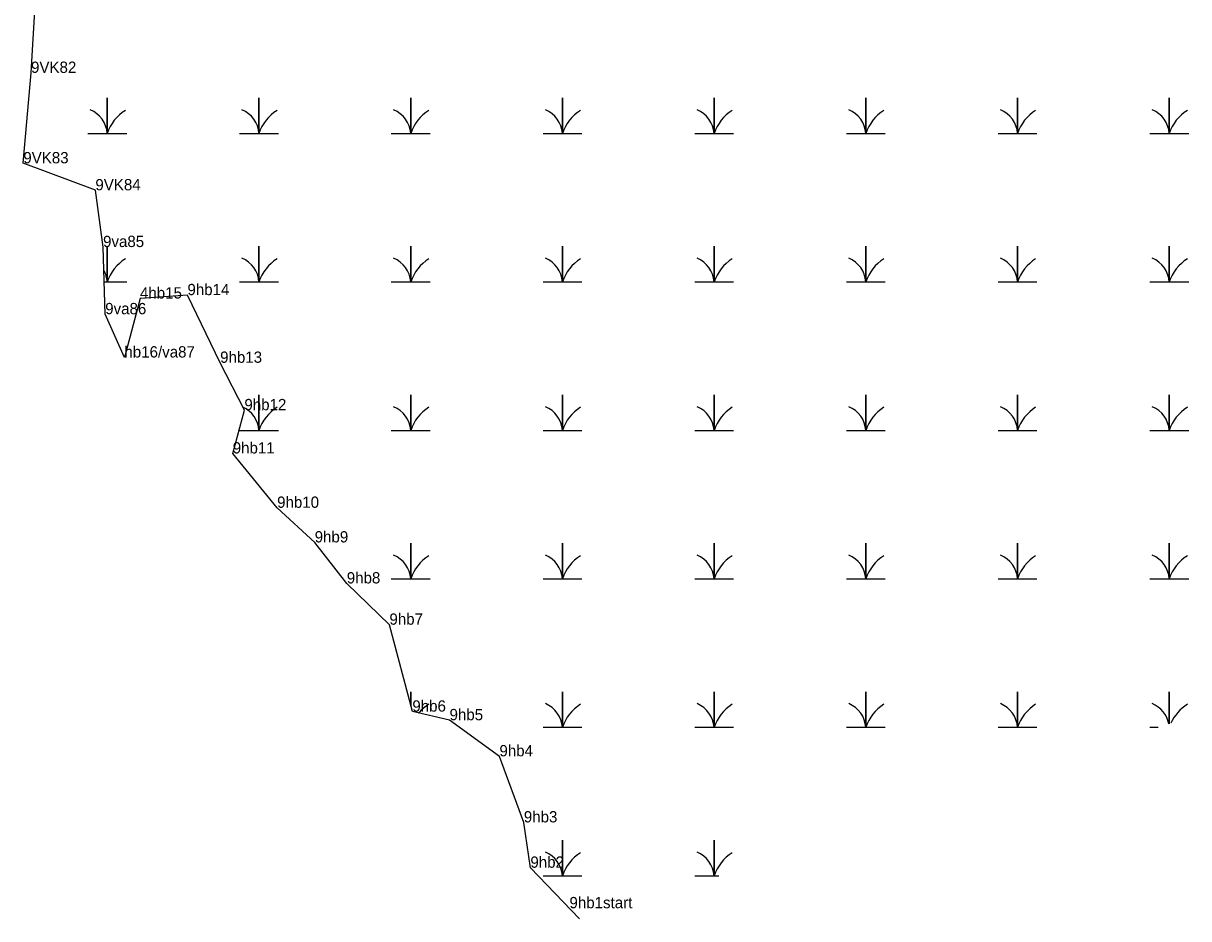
# Model space of a CAD drawing. Extents: x 2072529 to 2268796, y 436423 to 470406.
# Drawn here: x 2205507 to 2206024, y 446974 to 447371 of the extents above; entities that cross this region are included whole.
import ezdxf

# ---------------------------------------------------------------- set-up
doc = ezdxf.new("R2010")
doc.units = 0
for name, color, linetype in [('Exist Environmental Wetland Boundary Cogo Comment', 7, 'Continuous'), ('Exist Environmental Wetland Boundary Cogo Point CELL', 7, 'Continuous'), ('Old_Level_20', 7, 'Continuous')]:
    doc.layers.add(name, color=color, linetype=linetype)

msp = doc.modelspace()

# ---------------------------------------------------------------- linework, layer by layer
at = {"layer": 'Exist Environmental Wetland Boundary Cogo Point CELL'}
for points in [[(2205535.97, 447322.48), (2205544.57, 447322.48), (2205544.57, 447338.27), (2205544.57, 447322.48), (2205553.17, 447322.48)], [(2205603.22, 447322.48), (2205611.82, 447322.48), (2205611.82, 447338.27), (2205611.82, 447322.48), (2205620.42, 447322.48)], [(2205670.47, 447322.48), (2205679.07, 447322.48), (2205679.07, 447338.27), (2205679.07, 447322.48), (2205687.67, 447322.48)], [(2205737.72, 447322.48), (2205746.32, 447322.48), (2205746.32, 447338.27), (2205746.32, 447322.48), (2205754.92, 447322.48)], [(2205804.97, 447322.48), (2205813.57, 447322.48), (2205813.57, 447338.27), (2205813.57, 447322.48), (2205822.17, 447322.48)], [(2205872.22, 447322.48), (2205880.82, 447322.48), (2205880.82, 447338.27), (2205880.82, 447322.48), (2205889.42, 447322.48)], [(2205939.47, 447322.48), (2205948.07, 447322.48), (2205948.07, 447338.27), (2205948.07, 447322.48), (2205956.67, 447322.48)], [(2206006.72, 447322.48), (2206015.32, 447322.48), (2206015.32, 447338.27), (2206015.32, 447322.48), (2206023.92, 447322.48)], [(2205543.19, 447256.68), (2205544.57, 447256.68), (2205544.57, 447272.47), (2205544.57, 447256.68), (2205553.17, 447256.68)], [(2205603.22, 447256.68), (2205611.82, 447256.68), (2205611.82, 447272.47), (2205611.82, 447256.68), (2205620.42, 447256.68)], [(2205670.47, 447256.68), (2205679.07, 447256.68), (2205679.07, 447272.47), (2205679.07, 447256.68), (2205687.67, 447256.68)], [(2205737.72, 447256.68), (2205746.32, 447256.68), (2205746.32, 447272.47), (2205746.32, 447256.68), (2205754.92, 447256.68)], [(2205804.97, 447256.68), (2205813.57, 447256.68), (2205813.57, 447272.47), (2205813.57, 447256.68), (2205822.17, 447256.68)], [(2205872.22, 447256.68), (2205880.82, 447256.68), (2205880.82, 447272.47), (2205880.82, 447256.68), (2205889.42, 447256.68)], [(2205939.47, 447256.68), (2205948.07, 447256.68), (2205948.07, 447272.47), (2205948.07, 447256.68), (2205956.67, 447256.68)], [(2206006.72, 447256.68), (2206015.32, 447256.68), (2206015.32, 447272.47), (2206015.32, 447256.68), (2206023.92, 447256.68)], [(2205603.22, 447190.88), (2205611.82, 447190.88), (2205611.82, 447206.67), (2205611.82, 447190.88), (2205620.42, 447190.88)], [(2205670.47, 447190.88), (2205679.07, 447190.88), (2205679.07, 447206.67), (2205679.07, 447190.88), (2205687.67, 447190.88)], [(2205737.72, 447190.88), (2205746.32, 447190.88), (2205746.32, 447206.67), (2205746.32, 447190.88), (2205754.92, 447190.88)], [(2205804.97, 447190.88), (2205813.57, 447190.88), (2205813.57, 447206.67), (2205813.57, 447190.88), (2205822.17, 447190.88)], [(2205872.22, 447190.88), (2205880.82, 447190.88), (2205880.82, 447206.67), (2205880.82, 447190.88), (2205889.42, 447190.88)], [(2205939.47, 447190.88), (2205948.07, 447190.88), (2205948.07, 447206.67), (2205948.07, 447190.88), (2205956.67, 447190.88)], [(2206006.72, 447190.88), (2206015.32, 447190.88), (2206015.32, 447206.67), (2206015.32, 447190.88), (2206023.92, 447190.88)], [(2205670.47, 447125.08), (2205679.07, 447125.08), (2205679.07, 447140.87), (2205679.07, 447125.08), (2205687.67, 447125.08)], [(2205737.72, 447125.08), (2205746.32, 447125.08), (2205746.32, 447140.87), (2205746.32, 447125.08), (2205754.92, 447125.08)], [(2205804.97, 447125.08), (2205813.57, 447125.08), (2205813.57, 447140.87), (2205813.57, 447125.08), (2205822.17, 447125.08)], [(2205872.22, 447125.08), (2205880.82, 447125.08), (2205880.82, 447140.87), (2205880.82, 447125.08), (2205889.42, 447125.08)], [(2205939.47, 447125.08), (2205948.07, 447125.08), (2205948.07, 447140.87), (2205948.07, 447125.08), (2205956.67, 447125.08)], [(2206006.72, 447125.08), (2206015.32, 447125.08), (2206015.32, 447140.87), (2206015.32, 447125.08), (2206023.92, 447125.08)], [(2205679.07, 447069), (2205679.07, 447075.07), (2205679.07, 447069)], [(2205737.72, 447059.28), (2205746.32, 447059.28), (2205746.32, 447075.07), (2205746.32, 447059.28), (2205754.92, 447059.28)], [(2205804.97, 447059.28), (2205813.57, 447059.28), (2205813.57, 447075.07), (2205813.57, 447059.28), (2205822.17, 447059.28)], [(2205872.22, 447059.28), (2205880.82, 447059.28), (2205880.82, 447075.07), (2205880.82, 447059.28), (2205889.42, 447059.28)], [(2205939.47, 447059.28), (2205948.07, 447059.28), (2205948.07, 447075.07), (2205948.07, 447059.28), (2205956.67, 447059.28)], [(2206015.32, 447060.85), (2206015.32, 447075.07), (2206015.32, 447060.85)], [(2206006.72, 447059.28), (2206010.36, 447059.28)], [(2205737.72, 446993.48), (2205746.32, 446993.48), (2205746.32, 447009.27), (2205746.32, 446993.48), (2205754.92, 446993.48)], [(2205804.97, 446993.48), (2205813.57, 446993.48), (2205813.57, 447009.27), (2205813.57, 446993.48), (2205815.68, 446993.48)]]:
    msp.add_lwpolyline(points, dxfattribs=at)
for centre, radius, start, end in [((2205532.3, 447321.6), 12.3, 4.1403, 67.535), ((2205562.81, 447316.42), 19.22, 122.1274, 161.6222), ((2205599.55, 447321.6), 12.3, 4.1403, 67.535), ((2205630.06, 447316.42), 19.22, 122.1274, 161.6222), ((2205666.8, 447321.6), 12.3, 4.1403, 67.535), ((2205697.31, 447316.42), 19.22, 122.1274, 161.6222), ((2205734.05, 447321.6), 12.3, 4.1403, 67.535), ((2205764.56, 447316.42), 19.22, 122.1274, 161.6222), ((2205801.3, 447321.6), 12.3, 4.1403, 67.535), ((2205831.81, 447316.42), 19.22, 122.1274, 161.6222), ((2205868.55, 447321.6), 12.3, 4.1403, 67.535), ((2205899.06, 447316.42), 19.22, 122.1274, 161.6222), ((2205935.8, 447321.6), 12.3, 4.1403, 67.535), ((2205966.31, 447316.42), 19.22, 122.1274, 161.6222), ((2206003.05, 447321.6), 12.3, 4.1403, 67.535), ((2206033.56, 447316.42), 19.22, 122.1274, 161.6222), ((2205562.81, 447250.62), 19.22, 122.1274, 161.6222), ((2205599.55, 447255.8), 12.3, 4.1403, 67.535), ((2205630.06, 447250.62), 19.22, 122.1274, 161.6222), ((2205666.8, 447255.8), 12.3, 4.1403, 67.535), ((2205697.31, 447250.62), 19.22, 122.1274, 161.6222), ((2205734.05, 447255.8), 12.3, 4.1403, 67.535), ((2205764.56, 447250.62), 19.22, 122.1274, 161.6222), ((2205801.3, 447255.8), 12.3, 4.1403, 67.535), ((2205831.81, 447250.62), 19.22, 122.1274, 161.6222), ((2205868.55, 447255.8), 12.3, 4.1403, 67.535), ((2205899.06, 447250.62), 19.22, 122.1274, 161.6222), ((2205935.8, 447255.8), 12.3, 4.1403, 67.535), ((2205966.31, 447250.62), 19.22, 122.1274, 161.6222), ((2206003.05, 447255.8), 12.3, 4.1403, 67.535), ((2206033.56, 447250.62), 19.22, 122.1274, 161.6222), ((2205532.3, 447255.8), 12.3, 4.1403, 29.2758), ((2205599.55, 447190), 12.3, 4.1403, 65.5524), ((2205630.06, 447184.82), 19.22, 122.1274, 161.6222), ((2205666.8, 447190), 12.3, 4.1403, 67.535), ((2205697.31, 447184.82), 19.22, 122.1274, 161.6222), ((2205734.05, 447190), 12.3, 4.1403, 67.535), ((2205764.56, 447184.82), 19.22, 122.1274, 161.6222), ((2205801.3, 447190), 12.3, 4.1403, 67.535), ((2205831.81, 447184.82), 19.22, 122.1274, 161.6222), ((2205868.55, 447190), 12.3, 4.1403, 67.535), ((2205899.06, 447184.82), 19.22, 122.1274, 161.6222), ((2205935.8, 447190), 12.3, 4.1403, 67.535), ((2205966.31, 447184.82), 19.22, 122.1274, 161.6222), ((2206003.05, 447190), 12.3, 4.1403, 67.535), ((2206033.56, 447184.82), 19.22, 122.1274, 161.6222), ((2205666.8, 447124.2), 12.3, 4.1403, 67.535), ((2205697.31, 447119.02), 19.22, 122.1274, 161.6222), ((2205734.05, 447124.2), 12.3, 4.1403, 67.535), ((2205764.56, 447119.02), 19.22, 122.1274, 161.6222), ((2205801.3, 447124.2), 12.3, 4.1403, 67.535), ((2205831.81, 447119.02), 19.22, 122.1274, 161.6222), ((2205868.55, 447124.2), 12.3, 4.1403, 67.535), ((2205899.06, 447119.02), 19.22, 122.1274, 161.6222), ((2205935.8, 447124.2), 12.3, 4.1403, 67.535), ((2205966.31, 447119.02), 19.22, 122.1274, 161.6222), ((2206003.05, 447124.2), 12.3, 4.1403, 67.535), ((2206033.56, 447119.02), 19.22, 122.1274, 161.6222), ((2205697.31, 447053.22), 19.22, 122.1274, 139.9771), ((2205734.05, 447058.4), 12.3, 4.1403, 67.535), ((2205764.56, 447053.22), 19.22, 122.1274, 161.6222), ((2205801.3, 447058.4), 12.3, 4.1403, 67.535), ((2205831.81, 447053.22), 19.22, 122.1274, 161.6222), ((2205868.55, 447058.4), 12.3, 4.1403, 67.535), ((2205899.06, 447053.22), 19.22, 122.1274, 161.6222), ((2205935.8, 447058.4), 12.3, 4.1403, 67.535), ((2205966.31, 447053.22), 19.22, 122.1274, 161.6222), ((2206003.05, 447058.4), 12.3, 11.2135, 67.535), ((2206033.56, 447053.22), 19.22, 122.1274, 155.9041), ((2205734.05, 446992.6), 12.3, 4.1403, 67.535), ((2205764.56, 446987.42), 19.22, 122.1274, 161.6222), ((2205801.3, 446992.6), 12.3, 4.1403, 67.535), ((2205831.81, 446987.42), 19.22, 122.1274, 161.6222)]:
    msp.add_arc(centre, radius, start, end, dxfattribs=at)
at = {"layer": 'Old_Level_20'}
for p, q in [((2205510.77, 447349.31), (2205510.77, 447349.31)), ((2205507.35, 447309.23), (2205507.35, 447309.23)), ((2205539.3, 447297.26), (2205539.3, 447297.26)), ((2205542.7, 447272.12), (2205542.7, 447272.12)), ((2205542.7, 447272.12), (2205542.7, 447272.12)), ((2205559.08, 447249.3), (2205559.08, 447249.3)), ((2205559.08, 447249.3), (2205559.08, 447249.3)), ((2205580.1, 447250.8), (2205580.1, 447250.8)), ((2205580.1, 447250.8), (2205580.1, 447250.8)), ((2205543.65, 447242.35), (2205543.65, 447242.35)), ((2205543.65, 447242.35), (2205543.65, 447242.35)), ((2205552.17, 447223.17), (2205552.17, 447223.17)), ((2205552.17, 447223.17), (2205552.17, 447223.17)), ((2205594.59, 447220.82), (2205594.59, 447220.82)), ((2205594.59, 447220.82), (2205594.59, 447220.82)), ((2205605.35, 447199.81), (2205605.35, 447199.81)), ((2205605.35, 447199.81), (2205605.35, 447199.81)), ((2205600.18, 447180.63), (2205600.18, 447180.63)), ((2205600.18, 447180.63), (2205600.18, 447180.63)), ((2205619.85, 447156.56), (2205619.85, 447156.56)), ((2205619.85, 447156.56), (2205619.85, 447156.56)), ((2205636.51, 447141.22), (2205636.51, 447141.22)), ((2205636.51, 447141.22), (2205636.51, 447141.22)), ((2205650.73, 447123.04), (2205650.73, 447123.04)), ((2205650.73, 447123.04), (2205650.73, 447123.04)), ((2205669.63, 447104.75), (2205669.63, 447104.75)), ((2205669.63, 447104.75), (2205669.63, 447104.75)), ((2205679.8, 447066.23), (2205679.8, 447066.23)), ((2205679.8, 447066.23), (2205679.8, 447066.23)), ((2205696.29, 447062.42), (2205696.29, 447062.42)), ((2205696.29, 447062.42), (2205696.29, 447062.42)), ((2205718.39, 447046.41), (2205718.39, 447046.41)), ((2205718.39, 447046.41), (2205718.39, 447046.41)), ((2205729.21, 447017.14), (2205729.21, 447017.14)), ((2205729.21, 447017.14), (2205729.21, 447017.14)), ((2205732.12, 446997.05), (2205732.12, 446997.05)), ((2205732.12, 446997.05), (2205732.12, 446997.05)), ((2205749.44, 446979.1), (2205749.44, 446979.1)), ((2205749.44, 446979.1), (2205749.44, 446979.1))]:
    msp.add_line(p, q, dxfattribs=at)
for points in [[(2205552.17, 447223.17), (2205543.65, 447242.35), (2205542.7, 447272.12), (2205539.3, 447297.26), (2205507.35, 447309.23), (2205510.77, 447349.31), (2205512.65, 447379.36)], [(2205753.91, 446974.47), (2205732.12, 446997.05), (2205729.21, 447017.14), (2205718.39, 447046.41), (2205696.29, 447062.42), (2205679.8, 447066.23), (2205669.63, 447104.75), (2205650.73, 447123.04), (2205636.51, 447141.22), (2205619.85, 447156.56), (2205600.18, 447180.63), (2205605.35, 447199.81), (2205594.59, 447220.82), (2205580.1, 447250.8), (2205559.08, 447249.3), (2205552.17, 447223.17)]]:
    msp.add_lwpolyline(points, dxfattribs=at)

# ---------------------------------------------------------------- texts
at = {"layer": 'Exist Environmental Wetland Boundary Cogo Comment'}
for s, p in [('9VK82', (2205510.77, 447349.31)), ('9VK83', (2205507.35, 447309.23)), ('9VK84', (2205539.3, 447297.26)), ('9va85', (2205542.7, 447272.12)), ('4hb15', (2205559.08, 447249.3)), ('9hb14', (2205580.1, 447250.8)), ('9va86', (2205543.65, 447242.35)), ('hb16/va87', (2205552.17, 447223.17)), ('9hb13', (2205594.59, 447220.82)), ('9hb12', (2205605.35, 447199.81)), ('9hb11', (2205600.18, 447180.63)), ('9hb10', (2205619.85, 447156.56)), ('9hb9', (2205636.51, 447141.22)), ('9hb8', (2205650.73, 447123.04)), ('9hb7', (2205669.63, 447104.75)), ('9hb6', (2205679.8, 447066.23)), ('9hb5', (2205696.29, 447062.42)), ('9hb4', (2205718.39, 447046.41)), ('9hb3', (2205729.21, 447017.14)), ('9hb2', (2205732.12, 446997.05)), ('9hb1start', (2205749.44, 446979.1))]:
    msp.add_text(s, height=5, dxfattribs=at).set_placement(p)

doc.saveas('drawing.dxf')
